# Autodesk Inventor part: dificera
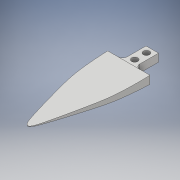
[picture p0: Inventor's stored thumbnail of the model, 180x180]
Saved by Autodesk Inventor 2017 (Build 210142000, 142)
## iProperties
Part Number: dificera
Material: Genérico
Document SubType Name: Modeling
Designer: Diego
Density: 1 g/cm^3
Appearance: Valor por defecto
Author: Diego
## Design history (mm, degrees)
sketch "Boceto1"
  geometry: L1 (-222.048, 262.042)-(-230.361, 793.579); L2 (-230.361, 793.579)-(125.176, 799.139); L3 (125.176, 799.139)-(133.489, 267.602); L4 (133.489, 267.602)-(-222.048, 262.042); L5 (0, 0)-(-18.209, 0); L6 (0, 0)-(16.898, 0); L7 (0, 0)-(0, -64.781); L8 (13.534, 0)-(13.534, -5.233); L9 (13.534, -5.233)-(13.145, -13.33); L10 (13.145, -13.33)-(12.653, -20.722); L11 (12.653, -20.722)-(11.033, -29.452); L12 (11.033, -29.452)-(9.292, -36.344); L13 (9.292, -36.344)-(6.37, -48.22); L14 (6.37, -48.22)-(3.751, -57.53); L15 (3.751, -57.53)-(2.202, -62.807); L16 (2.202, -62.807)-(0.931, -64.781); L17 (0.931, -64.781)-(0, -64.781); L18 (-6.37, -48.22)-(-3.751, -57.53); L19 (-13.534, 0)-(-13.534, -5.233); L20 (-13.534, -5.233)-(-13.145, -13.33); L21 (-13.145, -13.33)-(-12.653, -20.722); L22 (-12.653, -20.722)-(-11.033, -29.452); L23 (-11.033, -29.452)-(-9.292, -36.344); L24 (-9.292, -36.344)-(-6.37, -48.22); L25 (-3.751, -57.53)-(-2.202, -62.807); L26 (-2.202, -62.807)-(-0.931, -64.781); L27 (-0.931, -64.781)-(0, -64.781); L28 (-13.534, 0)-(13.534, 0); 1 further point; 1 other entity
  constraints: 10 symmetric about line, 8 end point, 3 horizontal, 2 point on line, 1 collinear, 1 perpendicular, 1 vertical, 8 other
extrude "Extrusión1" new body sketch "Boceto1" stored distance "d34" = 5; taper "d35" = 0 deg
node "Plano de trabajo1"
sketch "Boceto2"
  geometry: L1 (13.534, 0)-(-13.534, 0) reference; L2 (8.265, -64.781)-(-7.742, -64.781); 5 further points
  constraints: 2 end point, 2 horizontal, 1 coincident, 3 other
  node "Contorno proyectado1"
node "Plano de trabajo2"
feature "Dividir1"
mirror "Simetría1"
feature "Dividir2"
sketch "Boceto3"
  geometry: L1 (17.534, 5)-(9.534, 5); L2 (9.534, 5)-(9.534, 0); L3 (9.534, 0)-(17.534, 0); L4 (17.534, 0)-(17.534, 5); L5 (17.534, 5)-(9.534, 0); L6 (9.534, 5)-(17.534, 0); 1 further point
  constraints: 12 end point, 2 midpoint, 2 parallel, 1 horizontal, 1 perpendicular
  dimensions: "d46" = 8 distance of L3.end L2.end; "d47" = 5 distance of L2.end L1.end
extrude "Extrusión2" join sketch "Boceto3" distance "d48" = 15; taper "d49" = 0 deg
sketch "Boceto4"
  geometry: L1 (8, 0)-(0, 0) reference; L2 (8, 0)-(8, 15) reference; L3 (0, 15)-(8, 15) reference; L4 (0, 0)-(0, 15) reference; L5 (8, 15)-(0, 15) reference; L6 (4, 15)-(4, 0); L7 (4, 0)-(4, 7.5); L8 (4, 7.5)-(4, 15); L9 (4, 7.5)-(4, 0); C1 r 2 at (4, 11.25); C2 r 2 at (4, 3.75)
  constraints: 8 end point, 4 midpoint, 2 centre point, 2 collinear, 1 vertical
  dimensions: "d50" = 4 diameter of C1; "d51" = 4 diameter of C2
extrude "Extrusión3" cut sketch "Boceto4" distance "d52" = 15; taper "d53" = 0 deg
fillet "Empalme1" dims "d54" = 3
node "Sólido1"
node "Imagen1"
node "Plano de trabajo3"
node "Contorno proyectado2"
other parameters: "d45" = 0.15
